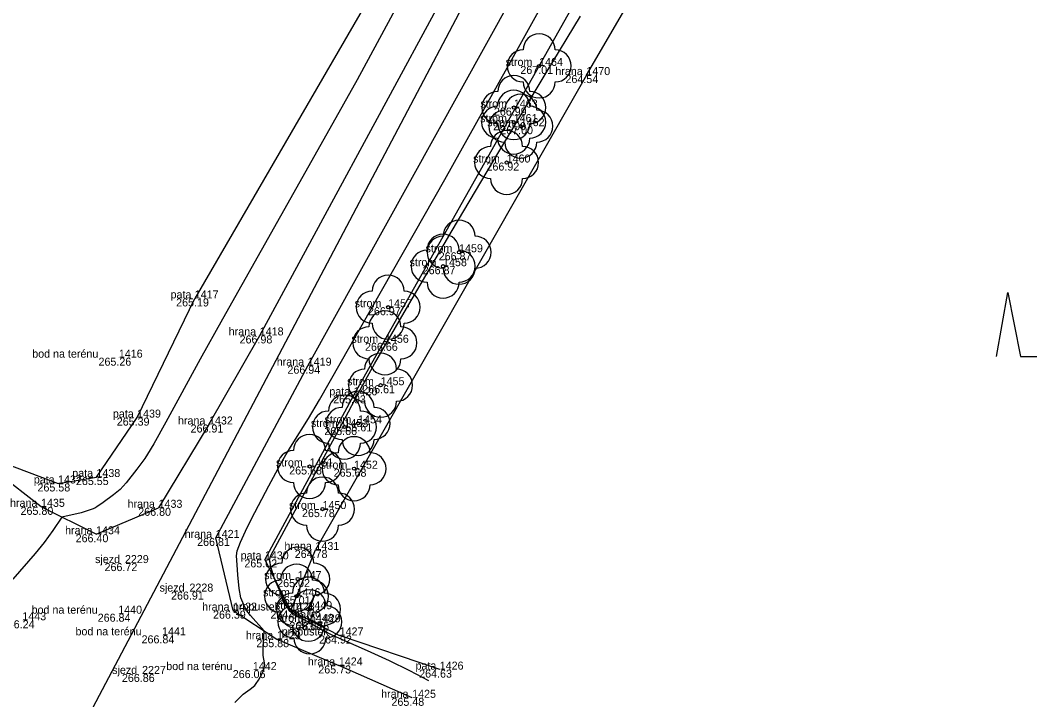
# Model space of a CAD drawing. Extents: x -567962 to -566460, y -1093720 to -1089838.
# Drawn here: x -567139.8 to -567076.4, y -1090786.7 to -1090744.3 of the extents above; entities that cross this region are included whole.
import ezdxf

# ---------------------------------------------------------------- set-up
doc = ezdxf.new("R2010")
doc.units = 0
for name, color, linetype in [('0_osa hráze', 7, 'Continuous'), ('bod_znacka', 7, 'Continuous'), ('cislo_bodu', 7, 'Continuous'), ('hlavni_vrst', 7, 'Continuous'), ('hrana_L', 7, 'Continuous'), ('kod_bodu', 7, 'Continuous'), ('norm_vrst', 7, 'Continuous'), ('ostatni', 7, 'Continuous'), ('propustky', 7, 'Continuous'), ('stromy', 7, 'Continuous'), ('Vrstva 1', 7, 'Continuous'), ('vyska_bodu', 7, 'Continuous')]:
    doc.layers.add(name, color=color, linetype=linetype)

# ---------------------------------------------------------------- blocks, each defined once
blk = doc.blocks.new('3.08')
at = {"layer": 'Vrstva 1'}
blk.add_lwpolyline([(-0.07, 0), (0, 0.4), (0.08, 0), (0.18, 0)], dxfattribs=at)

msp = doc.modelspace()

# ---------------------------------------------------------------- linework, layer by layer
at = {"layer": '0_osa hráze'}
msp.add_lwpolyline([(-567089.84, -1090700.38), (-567096.414, -1090713.39), (-567177.884, -1090867.779)], dxfattribs=at)
at = {"layer": 'bod_znacka'}
for p, q in [((-567107.44, -1090747.1), (-567107.44, -1090747.1)), ((-567104.49, -1090747.67), (-567104.49, -1090747.67)), ((-567109.02, -1090749.7), (-567109.02, -1090749.7)), ((-567109.03, -1090750.61), (-567109.03, -1090750.61)), ((-567108.59, -1090750.86), (-567108.59, -1090750.86)), ((-567109.47, -1090753.13), (-567109.47, -1090753.13)), ((-567112.44, -1090758.73), (-567112.44, -1090758.73)), ((-567113.44, -1090759.6), (-567113.44, -1090759.6)), ((-567128.95, -1090761.61), (-567128.95, -1090761.61)), ((-567116.87, -1090762.16), (-567116.87, -1090762.16)), ((-567124.89, -1090763.92), (-567124.89, -1090763.92)), ((-567117.07, -1090764.38), (-567117.07, -1090764.38)), ((-567133.69, -1090765.31), (-567133.69, -1090765.31)), ((-567121.89, -1090765.81), (-567121.89, -1090765.81)), ((-567117.34, -1090767.03), (-567117.34, -1090767.03)), ((-567119.03, -1090767.66), (-567119.03, -1090767.66)), ((-567132.55, -1090769.05), (-567132.55, -1090769.05)), ((-567128.06, -1090769.48), (-567128.06, -1090769.48)), ((-567118.75, -1090769.41), (-567118.75, -1090769.41)), ((-567119.6, -1090769.64), (-567119.6, -1090769.64)), ((-567121.78, -1090772.1), (-567121.78, -1090772.1)), ((-567119, -1090772.24), (-567119, -1090772.24)), ((-567137.49, -1090773.16), (-567137.49, -1090773.16)), ((-567135.09, -1090772.76), (-567135.09, -1090772.76)), ((-567138.55, -1090774.62), (-567138.55, -1090774.62)), ((-567131.21, -1090774.68), (-567131.21, -1090774.68)), ((-567120.97, -1090774.76), (-567120.97, -1090774.76)), ((-567135.11, -1090776.33), (-567135.11, -1090776.33)), ((-567127.64, -1090776.56), (-567127.64, -1090776.56)), ((-567121.41, -1090777.31), (-567121.41, -1090777.31)), ((-567133.31, -1090778.13), (-567133.31, -1090778.13)), ((-567124.57, -1090777.9), (-567124.57, -1090777.9)), ((-567122.52, -1090779.13), (-567122.52, -1090779.13)), ((-567129.28, -1090779.91), (-567129.28, -1090779.91)), ((-567122.59, -1090780.2), (-567122.59, -1090780.2)), ((-567133.73, -1090781.29), (-567133.73, -1090781.29)), ((-567126.55, -1090781.1), (-567126.55, -1090781.1)), ((-567122.95, -1090781.09), (-567122.95, -1090781.09)), ((-567121.85, -1090781.01), (-567121.85, -1090781.01)), ((-567139.72, -1090781.7), (-567139.72, -1090781.7)), ((-567121.76, -1090781.8), (-567121.76, -1090781.8)), ((-567121.32, -1090781.83), (-567121.32, -1090781.83)), ((-567130.99, -1090782.64), (-567130.99, -1090782.64)), ((-567119.9, -1090782.65), (-567119.9, -1090782.65)), ((-567123.82, -1090782.88), (-567123.82, -1090782.88)), ((-567119.95, -1090784.52), (-567119.95, -1090784.52)), ((-567132.24, -1090785.05), (-567132.24, -1090785.05)), ((-567125.32, -1090784.81), (-567125.32, -1090784.81)), ((-567113.65, -1090784.78), (-567113.65, -1090784.78)), ((-567115.37, -1090786.54), (-567115.37, -1090786.54))]:
    msp.add_line(p, q, dxfattribs=at)
at = {"layer": 'hlavni_vrst'}
msp.add_lwpolyline([(-567114.326, -1090785.471), (-567115.523, -1090784.854), (-567116.789, -1090784.239), (-567118.158, -1090783.613), (-567120.095, -1090782.76), (-567120.325, -1090782.651), (-567120.883, -1090782.357), (-567122.536, -1090781.447), (-567122.88, -1090781.236), (-567123.03, -1090781.133), (-567123.138, -1090780.935), (-567123.425, -1090780.332), (-567123.883, -1090779.298), (-567123.984, -1090779.053), (-567124.172, -1090778.432), (-567124.277, -1090777.934), (-567124.194, -1090777.661), (-567119.348, -1090768.696), (-567118.719, -1090767.51), (-567117.723, -1090765.703), (-567115.871, -1090762.491), (-567112.866, -1090757.368), (-567109.955, -1090752.465), (-567106.993, -1090747.53), (-567104.847, -1090743.983)], dxfattribs=at)
at = {"layer": 'hrana_L'}
for p, q in [((-567104.49, -1090747.67), (-567086.62, -1090717.11)), ((-567114.97, -1090737.52), (-567128.95, -1090761.61)), ((-567124.89, -1090763.92), (-567111.48, -1090739.19)), ((-567121.89, -1090765.81), (-567108.07, -1090740.92)), ((-567105.09, -1090742.9), (-567119.03, -1090767.66)), ((-567104.49, -1090747.67), (-567121.41, -1090777.31)), ((-567132.55, -1090769.05), (-567128.95, -1090761.61)), ((-567128.06, -1090769.48), (-567124.89, -1090763.92)), ((-567127.64, -1090776.56), (-567121.89, -1090765.81)), ((-567119.03, -1090767.66), (-567124.57, -1090777.9)), ((-567135.09, -1090772.76), (-567132.55, -1090769.05)), ((-567128.06, -1090769.48), (-567131.21, -1090774.68)), ((-567143.21, -1090771.01), (-567137.49, -1090773.16)), ((-567138.55, -1090774.62), (-567143.21, -1090771.01)), ((-567137.49, -1090773.16), (-567135.09, -1090772.76)), ((-567135.11, -1090776.33), (-567138.55, -1090774.62)), ((-567135.11, -1090776.33), (-567131.21, -1090774.68)), ((-567126.55, -1090781.1), (-567127.64, -1090776.56)), ((-567122.95, -1090781.09), (-567121.41, -1090777.31)), ((-567122.95, -1090781.09), (-567124.57, -1090777.9)), ((-567126.55, -1090781.1), (-567123.82, -1090782.88)), ((-567113.65, -1090784.78), (-567119.9, -1090782.65)), ((-567123.82, -1090782.88), (-567119.95, -1090784.52)), ((-567115.37, -1090786.54), (-567119.95, -1090784.52))]:
    msp.add_line(p, q, dxfattribs=at)
at = {"layer": 'norm_vrst'}
for points in [[(-567126.449, -1090786.829), (-567126.08, -1090786.461), (-567125.928, -1090786.32), (-567125.479, -1090785.996), (-567125.204, -1090785.769), (-567125.105, -1090785.654), (-567124.959, -1090785.444), (-567124.76, -1090785.059), (-567124.631, -1090784.788), (-567124.581, -1090784.51), (-567124.613, -1090784.225), (-567124.658, -1090784.029), (-567124.671, -1090783.88), (-567124.679, -1090783.369), (-567124.615, -1090782.362), (-567125.468, -1090781.407), (-567125.689, -1090781.121), (-567125.791, -1090780.918), (-567126.065, -1090780.304), (-567126.174, -1090779.725), (-567126.262, -1090778.855), (-567126.309, -1090778.244), (-567126.332, -1090777.679), (-567126.293, -1090777.372), (-567126.102, -1090776.826), (-567125.78, -1090776.138), (-567125.397, -1090775.361), (-567124.327, -1090773.301), (-567123.6, -1090771.962), (-567123.259, -1090771.372), (-567122.872, -1090770.732), (-567121.854, -1090769.115), (-567121.154, -1090767.951), (-567113.331, -1090754.184), (-567108.933, -1090746.325), (-567106.332, -1090741.622)], [(-567116.3, -1090743.343), (-567118.812, -1090747.963), (-567119.659, -1090749.49), (-567122.379, -1090754.341), (-567127.222, -1090762.9), (-567128.607, -1090765.399), (-567130.748, -1090769.34), (-567131.499, -1090770.677), (-567131.89, -1090771.324), (-567132.068, -1090771.595), (-567132.56, -1090772.262), (-567133.237, -1090773.127), (-567133.606, -1090773.533), (-567134.02, -1090773.868), (-567134.667, -1090774.352), (-567135.055, -1090774.621), (-567135.197, -1090774.695), (-567135.347, -1090774.76), (-567136.052, -1090774.994), (-567137.249, -1090775.267), (-567137.804, -1090776.094), (-567138.36, -1090776.839), (-567138.926, -1090777.529), (-567140.312, -1090779.127)], [(-567120.807, -1090782.126), (-567121.861, -1090781.587), (-567121.884, -1090781.497), (-567121.864, -1090781.227), (-567121.797, -1090780.89), (-567121.703, -1090780.653), (-567121.606, -1090780.444), (-567121.356, -1090779.998)]]:
    msp.add_lwpolyline(points, dxfattribs=at)
at = {"layer": 'propustky'}
msp.add_line((-567122.95, -1090781.09), (-567119.9, -1090782.65), dxfattribs=at)
at = {"layer": 'stromy'}
for centre in [(-567107.44, -1090747.1), (-567109.02, -1090749.7), (-567109.03, -1090750.61), (-567108.59, -1090750.86), (-567109.47, -1090753.13), (-567112.44, -1090758.73), (-567113.44, -1090759.6), (-567116.87, -1090762.16), (-567117.07, -1090764.38), (-567117.34, -1090767.03), (-567118.75, -1090769.41), (-567119.6, -1090769.64), (-567121.78, -1090772.1), (-567119, -1090772.24), (-567120.97, -1090774.76), (-567122.52, -1090779.13), (-567122.59, -1090780.2), (-567121.85, -1090781.01), (-567121.76, -1090781.8)]:
    msp.add_circle(centre, 0.1, dxfattribs=at)
for centre, start, end in [((-567107.44, -1090746.1), 0, 180), ((-567108.44, -1090747.1), 90, 270), ((-567106.44, -1090747.1), 270, 90), ((-567109.02, -1090748.7), 0, 180), ((-567107.44, -1090748.1), 180, 0), ((-567110.02, -1090749.7), 90, 270), ((-567109.03, -1090749.61), 0, 180), ((-567108.59, -1090749.86), 0, 180), ((-567108.02, -1090749.7), 270, 90), ((-567110.03, -1090750.61), 90, 270), ((-567108.03, -1090750.61), 270, 90), ((-567109.59, -1090750.86), 90, 270), ((-567107.59, -1090750.86), 270, 90), ((-567109.02, -1090750.7), 180, 0), ((-567109.47, -1090752.13), 0, 180), ((-567109.03, -1090751.61), 180, 0), ((-567110.47, -1090753.13), 90, 270), ((-567108.59, -1090751.86), 180, 0), ((-567108.47, -1090753.13), 270, 90), ((-567109.47, -1090754.13), 180, 0), ((-567112.44, -1090757.73), 0, 180), ((-567113.44, -1090758.6), 0, 180), ((-567113.44, -1090758.73), 90, 270), ((-567111.44, -1090758.73), 270, 90), ((-567114.44, -1090759.6), 90, 270), ((-567112.44, -1090759.6), 270, 90), ((-567112.44, -1090759.73), 180, 0), ((-567116.87, -1090761.16), 0, 180), ((-567113.44, -1090760.6), 180, 0), ((-567117.87, -1090762.16), 90, 270), ((-567115.87, -1090762.16), 270, 90), ((-567117.07, -1090763.38), 0, 180), ((-567118.07, -1090764.38), 90, 270), ((-567116.87, -1090763.16), 180, 0), ((-567116.07, -1090764.38), 270, 90), ((-567117.34, -1090766.03), 0, 180), ((-567117.07, -1090765.38), 180, 0), ((-567118.34, -1090767.03), 90, 270), ((-567116.34, -1090767.03), 270, 90), ((-567118.75, -1090768.41), 0, 180), ((-567119.6, -1090768.64), 0, 180), ((-567117.34, -1090768.03), 180, 0), ((-567120.6, -1090769.64), 90, 270), ((-567119.75, -1090769.41), 90, 270), ((-567118.6, -1090769.64), 270, 90), ((-567117.75, -1090769.41), 270, 90), ((-567121.78, -1090771.1), 0, 180), ((-567119.6, -1090770.64), 180, 0), ((-567119, -1090771.24), 0, 180), ((-567118.75, -1090770.41), 180, 0), ((-567122.78, -1090772.1), 90, 270), ((-567120, -1090772.24), 90, 270), ((-567120.78, -1090772.1), 270, 90), ((-567118, -1090772.24), 270, 90), ((-567121.78, -1090773.1), 180, 0), ((-567120.97, -1090773.76), 0, 180), ((-567119, -1090773.24), 180, 0), ((-567121.97, -1090774.76), 90, 270), ((-567119.97, -1090774.76), 270, 90), ((-567120.97, -1090775.76), 180, 0), ((-567122.52, -1090778.13), 0, 180), ((-567123.52, -1090779.13), 90, 270), ((-567122.59, -1090779.2), 0, 180), ((-567121.52, -1090779.13), 270, 90), ((-567121.85, -1090780.01), 0, 180), ((-567123.59, -1090780.2), 90, 270), ((-567121.59, -1090780.2), 270, 90), ((-567122.85, -1090781.01), 90, 270), ((-567122.52, -1090780.13), 180, 0), ((-567121.76, -1090780.8), 0, 180), ((-567120.85, -1090781.01), 270, 90), ((-567122.76, -1090781.8), 90, 270), ((-567120.76, -1090781.8), 270, 90), ((-567122.59, -1090781.2), 180, 0), ((-567121.85, -1090782.01), 180, 0), ((-567121.76, -1090782.8), 180, 0)]:
    msp.add_arc(centre, 1, start, end, dxfattribs=at)

# ---------------------------------------------------------------- block references
at = {"layer": 'ostatni', "xscale": 10, "yscale": 10}
msp.add_blockref('3.08', (-567078.165, -1090765.233), dxfattribs=at)

# ---------------------------------------------------------------- texts
at = {"layer": 'cislo_bodu'}
for s, p in [('1464', (-567107.44, -1090747.1)), ('1470', (-567104.49, -1090747.67)), ('1463', (-567109.02, -1090749.7)), ('1461', (-567109.03, -1090750.61)), ('1462', (-567108.59, -1090750.86)), ('1460', (-567109.47, -1090753.13)), ('1459', (-567112.44, -1090758.73)), ('1458', (-567113.44, -1090759.6)), ('1417', (-567128.95, -1090761.61)), ('1457', (-567116.87, -1090762.16)), ('1418', (-567124.89, -1090763.92)), ('1456', (-567117.07, -1090764.38)), ('1416', (-567133.69, -1090765.31)), ('1419', (-567121.89, -1090765.81)), ('1455', (-567117.34, -1090767.03)), ('1420', (-567119.03, -1090767.66)), ('1439', (-567132.55, -1090769.05)), ('1432', (-567128.06, -1090769.48)), ('1453', (-567119.6, -1090769.64)), ('1454', (-567118.75, -1090769.41)), ('1451', (-567121.78, -1090772.1)), ('1452', (-567119, -1090772.24)), ('1437', (-567137.49, -1090773.16)), ('1438', (-567135.09, -1090772.76)), ('1435', (-567138.55, -1090774.62)), ('1433', (-567131.21, -1090774.68)), ('1450', (-567120.97, -1090774.76)), ('1434', (-567135.11, -1090776.33)), ('1421', (-567127.64, -1090776.56)), ('1431', (-567121.41, -1090777.31)), ('2229', (-567133.31, -1090778.13)), ('1430', (-567124.57, -1090777.9)), ('1447', (-567122.52, -1090779.13)), ('2228', (-567129.28, -1090779.91)), ('1446', (-567122.59, -1090780.2)), ('1440', (-567133.73, -1090781.29)), ('1422', (-567126.55, -1090781.1)), ('1428', (-567122.95, -1090781.09)), ('1449', (-567121.85, -1090781.01)), ('1443', (-567139.72, -1090781.7)), ('1448', (-567121.76, -1090781.8)), ('1429', (-567121.32, -1090781.83)), ('1441', (-567130.99, -1090782.64)), ('1427', (-567119.9, -1090782.65)), ('1423', (-567123.82, -1090782.88)), ('1424', (-567119.95, -1090784.52)), ('2227', (-567132.24, -1090785.05)), ('1442', (-567125.32, -1090784.81)), ('1426', (-567113.65, -1090784.78)), ('1425', (-567115.37, -1090786.54))]:
    msp.add_text(s, height=0.5, dxfattribs=at).set_placement(p)
at = {"layer": 'kod_bodu'}
for s, p in [('strom', (-567109.534, -1090747.1)), ('hrana', (-567106.427, -1090747.67)), ('strom', (-567111.114, -1090749.7)), ('strom', (-567111.124, -1090750.61)), ('strom', (-567110.684, -1090750.86)), ('strom', (-567111.564, -1090753.13)), ('strom', (-567114.534, -1090758.73)), ('strom', (-567115.534, -1090759.6)), ('pata', (-567130.462, -1090761.61)), ('strom', (-567118.964, -1090762.16)), ('hrana', (-567126.827, -1090763.92)), ('strom', (-567119.164, -1090764.38)), ('bod na terénu', (-567139.099, -1090765.31)), ('hrana', (-567123.827, -1090765.81)), ('strom', (-567119.434, -1090767.03)), ('pata', (-567120.542, -1090767.66)), ('pata', (-567134.062, -1090769.05)), ('hrana', (-567129.997, -1090769.48)), ('strom', (-567121.694, -1090769.64)), ('strom', (-567120.844, -1090769.41)), ('strom', (-567123.874, -1090772.1)), ('strom', (-567121.094, -1090772.24)), ('pata', (-567136.602, -1090772.76)), ('pata', (-567139.002, -1090773.16)), ('hrana', (-567140.487, -1090774.62)), ('hrana', (-567133.147, -1090774.68)), ('strom', (-567123.064, -1090774.76)), ('hrana', (-567137.047, -1090776.33)), ('hrana', (-567129.577, -1090776.56)), ('hrana', (-567123.347, -1090777.31)), ('sjezd', (-567135.176, -1090778.13)), ('pata', (-567126.082, -1090777.9)), ('strom', (-567124.614, -1090779.13)), ('sjezd', (-567131.146, -1090779.91)), ('strom', (-567124.684, -1090780.2)), ('bod na terénu', (-567139.139, -1090781.29)), ('hrana', (-567128.487, -1090781.1)), ('propustek', (-567126.564, -1090781.09)), ('strom', (-567123.944, -1090781.01)), ('strom', (-567123.854, -1090781.8)), ('dno', (-567122.501, -1090781.83)), ('bod na terénu', (-567136.399, -1090782.64)), ('propustek', (-567123.514, -1090782.65)), ('hrana', (-567125.757, -1090782.88)), ('hrana', (-567121.887, -1090784.52)), ('sjezd', (-567134.106, -1090785.05)), ('bod na terénu', (-567130.729, -1090784.81)), ('pata', (-567115.162, -1090784.78)), ('hrana', (-567117.307, -1090786.54))]:
    msp.add_text(s, height=0.5, dxfattribs=at).set_placement(p)
at = {"layer": 'vyska_bodu'}
for s, p in [('267.01', (-567108.613, -1090747.6)), ('264.54', (-567105.795, -1090748.17)), ('266.99', (-567110.266, -1090750.2)), ('267.00', (-567110.309, -1090751.11)), ('267.00', (-567109.869, -1090751.36)), ('266.92', (-567110.728, -1090753.63)), ('266.87', (-567113.712, -1090759.23)), ('266.87', (-567114.712, -1090760.1)), ('265.19', (-567130.111, -1090762.11)), ('266.97', (-567118.13, -1090762.66)), ('266.98', (-567126.148, -1090764.42)), ('266.66', (-567118.316, -1090764.88)), ('265.26', (-567134.96, -1090765.81)), ('266.94', (-567123.16, -1090766.31)), ('266.61', (-567118.489, -1090767.53)), ('265.03', (-567120.309, -1090768.16)), ('265.39', (-567133.82, -1090769.55)), ('266.91', (-567129.209, -1090769.98)), ('265.61', (-567119.911, -1090769.91)), ('265.66', (-567120.858, -1090770.14)), ('265.68', (-567123.05, -1090772.6)), ('265.68', (-567120.27, -1090772.74)), ('265.58', (-567138.771, -1090773.66)), ('265.55', (-567136.371, -1090773.26)), ('265.80', (-567139.829, -1090775.12)), ('266.80', (-567132.478, -1090775.18)), ('265.78', (-567122.253, -1090775.26)), ('266.40', (-567136.389, -1090776.83)), ('266.81', (-567128.801, -1090777.06)), ('264.78', (-567122.705, -1090777.81)), ('266.72', (-567134.582, -1090778.63)), ('265.02', (-567125.849, -1090778.4)), ('265.02', (-567123.799, -1090779.63)), ('266.91', (-567130.429, -1090780.41)), ('265.01', (-567123.761, -1090780.7)), ('266.84', (-567135.011, -1090781.79)), ('266.39', (-567127.808, -1090781.6)), ('264.96', (-567124.22, -1090781.59)), ('265.06', (-567123.118, -1090781.51)), ('266.24', (-567141.001, -1090782.2)), ('265.08', (-567123.039, -1090782.3)), ('263.75', (-567122.603, -1090782.33)), ('266.84', (-567132.271, -1090783.14)), ('264.92', (-567121.181, -1090783.15)), ('265.88', (-567125.101, -1090783.38)), ('265.73', (-567121.233, -1090785.02)), ('266.86', (-567133.498, -1090785.55)), ('266.06', (-567126.576, -1090785.31)), ('264.63', (-567114.931, -1090785.28)), ('265.48', (-567116.663, -1090787.04))]:
    msp.add_text(s, height=0.5, dxfattribs=at).set_placement(p)

doc.saveas('drawing.dxf')
